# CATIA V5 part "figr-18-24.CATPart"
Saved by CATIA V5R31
Part number: Part1
Bounding box of the stored display mesh (mm): x 0 to 100, y -127 to 127, z -16 to 0
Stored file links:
  D:\PROJECTS\Project 2021\US EDITION\CATIA V5 6R 2021\Resources\Part Files\c18_catia_v6_6r2021_prt\figr-18-24.CATPart
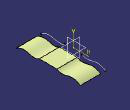
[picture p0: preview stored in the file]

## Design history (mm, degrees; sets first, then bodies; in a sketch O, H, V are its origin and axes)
Body1 (main body)
  Sketch1 on yz-plane, origin (0, 0, 0), H (0, 1, 0), V (0, 0, 1)
    spline S1 through (-127, -16) (-75, -8) (-52.8201, -11.5937) (-35, -5.5937)
    spline S2 through (127, -16) (75, -8) (52.8201, -11.5937) (35, -5.5937)
    point P1 (-35, -5.5937)
    point P2 (35, -5.5937)
    point P3 (-127, -16)
    point P4 (127, -16)
    point P5 (-52.8201, -11.5937)
    point P6 (52.8201, -11.5937)
    point P7 (-75, -8)
    point P8 (75, -8)
    symmetry: S1 S2 V, P1 P2 V, P3 P4 V, P5 P6 V, P7 P8 V
  Extrude1: Element1 Sketch1, Lim1 20, Lim2 -100
  DatumSurface1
